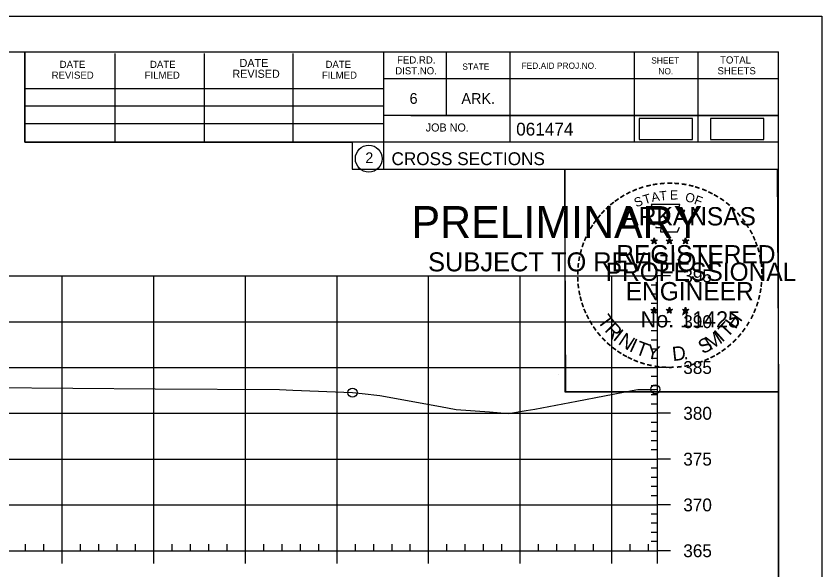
# Model space of a CAD drawing. Extents: x 1359801 to 1362404, y 372415 to 374228.
# Drawn here: x 1361894.9 to 1361982.8, y 372674.2 to 372734.6 of the extents above; entities that cross this region are included whole.
import ezdxf

# ---------------------------------------------------------------- set-up
doc = ezdxf.new("R2010")
doc.units = 0
for name, color, linetype in [('S_DRG_PT_SYM', 7, 'Continuous'), ('S_MAILBOX', 7, 'Continuous'), ('S_PRIMARY_CTL', 7, 'Continuous'), ('S_PRIMARY_CTL_ANNOT', 7, 'Continuous'), ('S_SHOULDER', 7, 'Continuous'), ('S_TELEPHONE_UTILITIES', 7, 'Continuous'), ('S_UNDERGROUND_CABLE', 7, 'Continuous'), ('S_UTL_PT_SYM', 7, 'Continuous'), ('S_WATER_UTILITIES', 7, 'Continuous')]:
    doc.layers.add(name, color=color, linetype=linetype)

msp = doc.modelspace()

# ---------------------------------------------------------------- linework, layer by layer
at = {"layer": 'S_DRG_PT_SYM'}
msp.add_lwpolyline([(1361821.284, 372693.939), (1361856.016, 372694.14), (1361874.05, 372694.226), (1361910.048, 372693.936), (1361923.612, 372693.836), (1361925.075, 372693.774), (1361931.575, 372693.503), (1361932.614, 372693.403), (1361934.572, 372693.207), (1361941.182, 372691.986), (1361942.877, 372691.662), (1361946.529, 372691.397), (1361948.625, 372691.234), (1361950.541, 372691.539), (1361951.497, 372691.687), (1361956.053, 372692.567), (1361962.106, 372693.736), (1361962.718, 372693.849), (1361962.822, 372693.849), (1361964.639, 372693.862), (1361964.89, 372693.87)], dxfattribs=at)
at = {"layer": 'S_MAILBOX'}
for p, q in [((1361674.89, 372706.246), (1361964.89, 372706.246)), ((1361899.89, 372676.246), (1361899.89, 372706.246)), ((1361909.89, 372676.246), (1361909.89, 372706.246)), ((1361919.89, 372676.246), (1361919.89, 372706.246)), ((1361929.89, 372676.246), (1361929.89, 372706.246)), ((1361939.89, 372676.246), (1361939.89, 372706.246)), ((1361949.89, 372676.246), (1361949.89, 372706.246)), ((1361959.89, 372676.246), (1361959.89, 372706.246)), ((1361964.89, 372676.246), (1361964.89, 372706.246)), ((1361674.89, 372701.246), (1361964.89, 372701.246)), ((1361674.89, 372696.246), (1361964.89, 372696.246)), ((1361674.89, 372691.246), (1361964.89, 372691.246)), ((1361674.89, 372686.246), (1361964.89, 372686.246)), ((1361674.89, 372681.246), (1361964.89, 372681.246)), ((1361674.89, 372676.246), (1361964.89, 372676.246))]:
    msp.add_line(p, q, dxfattribs=at)
at = {"layer": 'S_SHOULDER'}
for p, q in [((1361649.489, 372734.6), (1361982.823, 372734.6)), ((1361954.105, 372695.45), (1361954.105, 372695.45))]:
    msp.add_line(p, q, dxfattribs=at)
for points in [[(1361649.483, 372734.6), (1361982.823, 372734.6), (1361982.823, 372521.263), (1361649.483, 372521.263)], [(1361895.81, 372730.706), (1361895.81, 372720.826), (1361931.542, 372720.826), (1361931.542, 372717.906), (1361954.742, 372717.906), (1361954.742, 372693.573), (1361978.07, 372693.573), (1361978.07, 372525.246), (1361661.89, 372525.246), (1361661.89, 372730.706)], [(1361954.742, 372717.906), (1361977.95, 372717.906), (1361978.07, 372693.573), (1361954.862, 372693.573)]]:
    msp.add_lwpolyline(points, close=True, dxfattribs=at)
for centre in [(1361931.575, 372693.503), (1361964.639, 372693.862)]:
    msp.add_circle(centre, 0.5, dxfattribs=at)
at = {"layer": 'S_TELEPHONE_UTILITIES'}
for p, q in [((1361964.155, 372710.161), (1361964.504, 372710.05)), ((1361964.155, 372710.161), (1361964.408, 372710.116)), ((1361964.155, 372710.161), (1361964.392, 372710.039)), ((1361964.288, 372709.753), (1361964.504, 372710.05)), ((1361964.288, 372709.753), (1361964.414, 372709.997)), ((1361964.288, 372709.753), (1361964.502, 372709.97)), ((1361964.504, 372710.415), (1361964.463, 372710.163)), ((1361964.717, 372709.753), (1361964.502, 372709.967)), ((1361964.504, 372710.05), (1361964.504, 372710.415)), ((1361964.504, 372710.415), (1361964.553, 372710.165)), ((1361964.851, 372710.161), (1361964.504, 372710.05)), ((1361964.717, 372709.753), (1361964.504, 372710.05)), ((1361964.851, 372710.161), (1361964.565, 372710.112)), ((1361964.717, 372709.753), (1361964.58, 372710.044)), ((1361964.851, 372710.161), (1361964.647, 372710.059)), ((1361965.825, 372710.161), (1361966.174, 372710.05)), ((1361965.825, 372710.161), (1361966.078, 372710.116)), ((1361965.825, 372710.161), (1361966.062, 372710.039)), ((1361965.958, 372709.753), (1361966.174, 372710.05)), ((1361965.958, 372709.753), (1361966.084, 372709.997)), ((1361965.958, 372709.753), (1361966.172, 372709.97)), ((1361966.174, 372710.415), (1361966.133, 372710.163)), ((1361966.387, 372709.753), (1361966.172, 372709.967)), ((1361966.174, 372710.05), (1361966.174, 372710.415)), ((1361966.174, 372710.415), (1361966.223, 372710.165)), ((1361966.521, 372710.161), (1361966.174, 372710.05)), ((1361966.387, 372709.753), (1361966.174, 372710.05)), ((1361966.521, 372710.161), (1361966.235, 372710.112)), ((1361966.387, 372709.753), (1361966.25, 372710.044)), ((1361966.521, 372710.161), (1361966.317, 372710.059)), ((1361967.589, 372710.149), (1361967.938, 372710.038)), ((1361967.589, 372710.149), (1361967.842, 372710.104)), ((1361967.589, 372710.149), (1361967.826, 372710.027)), ((1361967.722, 372709.741), (1361967.938, 372710.038)), ((1361967.722, 372709.741), (1361967.848, 372709.985)), ((1361967.722, 372709.741), (1361967.936, 372709.958)), ((1361967.938, 372710.403), (1361967.897, 372710.151)), ((1361968.151, 372709.741), (1361967.936, 372709.955)), ((1361967.938, 372710.038), (1361967.938, 372710.403)), ((1361967.938, 372710.403), (1361967.987, 372710.153)), ((1361968.285, 372710.149), (1361967.938, 372710.038)), ((1361968.151, 372709.741), (1361967.938, 372710.038)), ((1361968.285, 372710.149), (1361967.999, 372710.1)), ((1361968.151, 372709.741), (1361968.014, 372710.032)), ((1361968.285, 372710.149), (1361968.081, 372710.047)), ((1361964.5, 372702.842), (1361964.459, 372702.59)), ((1361964.5, 372702.477), (1361964.5, 372702.842)), ((1361964.5, 372702.842), (1361964.549, 372702.592)), ((1361966.169, 372702.842), (1361966.128, 372702.59)), ((1361966.169, 372702.477), (1361966.169, 372702.842)), ((1361966.169, 372702.842), (1361966.218, 372702.592)), ((1361967.936, 372702.832), (1361967.895, 372702.58)), ((1361967.936, 372702.467), (1361967.936, 372702.832)), ((1361967.936, 372702.832), (1361967.985, 372702.582)), ((1361964.151, 372702.588), (1361964.5, 372702.477)), ((1361964.151, 372702.588), (1361964.404, 372702.543)), ((1361964.151, 372702.588), (1361964.388, 372702.466)), ((1361964.284, 372702.18), (1361964.5, 372702.477)), ((1361964.284, 372702.18), (1361964.41, 372702.424)), ((1361964.284, 372702.18), (1361964.498, 372702.397)), ((1361964.713, 372702.18), (1361964.498, 372702.394)), ((1361964.847, 372702.588), (1361964.5, 372702.477)), ((1361964.713, 372702.18), (1361964.5, 372702.477)), ((1361964.847, 372702.588), (1361964.561, 372702.539)), ((1361964.713, 372702.18), (1361964.576, 372702.471)), ((1361964.847, 372702.588), (1361964.643, 372702.486)), ((1361965.82, 372702.588), (1361966.169, 372702.477)), ((1361965.82, 372702.588), (1361966.073, 372702.543)), ((1361965.82, 372702.588), (1361966.057, 372702.466)), ((1361965.953, 372702.18), (1361966.169, 372702.477)), ((1361965.953, 372702.18), (1361966.079, 372702.424)), ((1361965.953, 372702.18), (1361966.167, 372702.397)), ((1361966.382, 372702.18), (1361966.167, 372702.394)), ((1361966.516, 372702.588), (1361966.169, 372702.477)), ((1361966.382, 372702.18), (1361966.169, 372702.477)), ((1361966.516, 372702.588), (1361966.23, 372702.539)), ((1361966.382, 372702.18), (1361966.245, 372702.471)), ((1361966.516, 372702.588), (1361966.312, 372702.486)), ((1361967.587, 372702.578), (1361967.936, 372702.467)), ((1361967.587, 372702.578), (1361967.84, 372702.533)), ((1361967.587, 372702.578), (1361967.824, 372702.456)), ((1361967.72, 372702.17), (1361967.936, 372702.467)), ((1361967.72, 372702.17), (1361967.846, 372702.414)), ((1361967.72, 372702.17), (1361967.934, 372702.387)), ((1361968.149, 372702.17), (1361967.934, 372702.384)), ((1361968.283, 372702.578), (1361967.936, 372702.467)), ((1361968.149, 372702.17), (1361967.936, 372702.467)), ((1361968.283, 372702.578), (1361967.997, 372702.529)), ((1361968.149, 372702.17), (1361968.012, 372702.461)), ((1361968.283, 372702.578), (1361968.079, 372702.476))]:
    msp.add_line(p, q, dxfattribs=at)
for points in [[(1361964.196, 372714.039), (1361964.465, 372713.212)], [(1361967.707, 372713.117), (1361967.849, 372713.401), (1361967.164, 372713.377), (1361967.312, 372714.039), (1361964.196, 372714.039)], [(1361964.688, 372711.616), (1361964.688, 372711.529), (1361965.251, 372711.51), (1361965.197, 372711.037), (1361967.067, 372711.037), (1361967.268, 372711.573)], [(1361964.504, 372710.415), (1361964.717, 372709.753), (1361964.155, 372710.161), (1361964.851, 372710.161), (1361964.288, 372709.753), (1361964.504, 372710.415)], [(1361966.174, 372710.415), (1361966.387, 372709.753), (1361965.825, 372710.161), (1361966.521, 372710.161), (1361965.958, 372709.753), (1361966.174, 372710.415)], [(1361967.938, 372710.403), (1361968.151, 372709.741), (1361967.589, 372710.149), (1361968.285, 372710.149), (1361967.722, 372709.741), (1361967.938, 372710.403)], [(1361964.5, 372702.842), (1361964.713, 372702.18), (1361964.151, 372702.588), (1361964.847, 372702.588), (1361964.284, 372702.18), (1361964.5, 372702.842)], [(1361966.169, 372702.842), (1361966.382, 372702.18), (1361965.82, 372702.588), (1361966.516, 372702.588), (1361965.953, 372702.18), (1361966.169, 372702.842)], [(1361967.936, 372702.832), (1361968.149, 372702.17), (1361967.587, 372702.578), (1361968.283, 372702.578), (1361967.72, 372702.17), (1361967.936, 372702.832)]]:
    msp.add_lwpolyline(points, dxfattribs=at)
for centre, radius in [((1361964.503, 372710.049), 0.172), ((1361964.503, 372710.049), 0.145), ((1361964.503, 372710.049), 0.116), ((1361964.503, 372710.049), 0.0991), ((1361964.503, 372710.049), 0.0747), ((1361964.503, 372710.049), 0.0495), ((1361964.503, 372710.049), 0.0296), ((1361966.173, 372710.049), 0.172), ((1361966.173, 372710.049), 0.145), ((1361966.173, 372710.049), 0.116), ((1361966.173, 372710.049), 0.0991), ((1361966.173, 372710.049), 0.0747), ((1361966.173, 372710.049), 0.0495), ((1361966.173, 372710.049), 0.0296), ((1361967.937, 372710.037), 0.172), ((1361967.937, 372710.037), 0.145), ((1361967.937, 372710.037), 0.116), ((1361967.937, 372710.037), 0.0991), ((1361967.937, 372710.037), 0.0747), ((1361967.937, 372710.037), 0.0495), ((1361967.937, 372710.037), 0.0296), ((1361964.499, 372702.476), 0.172), ((1361964.499, 372702.476), 0.145), ((1361964.499, 372702.476), 0.116), ((1361966.168, 372702.476), 0.172), ((1361966.168, 372702.476), 0.145), ((1361966.168, 372702.476), 0.116), ((1361967.935, 372702.466), 0.172), ((1361967.935, 372702.466), 0.145), ((1361964.499, 372702.476), 0.0991), ((1361964.499, 372702.476), 0.0747), ((1361964.499, 372702.476), 0.0495), ((1361964.499, 372702.476), 0.0296), ((1361966.168, 372702.476), 0.0991), ((1361966.168, 372702.476), 0.0747), ((1361966.168, 372702.476), 0.0495), ((1361966.168, 372702.476), 0.0296), ((1361967.935, 372702.466), 0.116), ((1361967.935, 372702.466), 0.0991), ((1361967.935, 372702.466), 0.0747), ((1361967.935, 372702.466), 0.0495), ((1361967.935, 372702.466), 0.0296)]:
    msp.add_circle(centre, radius, dxfattribs=at)
at = {"layer": 'S_UNDERGROUND_CABLE'}
for points in [[(1361962.88, 372721.124), (1361968.713, 372721.124), (1361968.713, 372723.434), (1361962.88, 372723.434)], [(1361970.649, 372721.13), (1361976.482, 372721.13), (1361976.482, 372723.44), (1361970.649, 372723.44)]]:
    msp.add_lwpolyline(points, close=True, dxfattribs=at)
at = {"layer": 'S_UTL_PT_SYM'}
for p, q in [((1361661.89, 372730.706), (1361978.07, 372730.706)), ((1361895.81, 372720.826), (1361895.81, 372730.706)), ((1361905.67, 372720.826), (1361905.67, 372730.506)), ((1361915.43, 372720.826), (1361915.43, 372730.506)), ((1361925.11, 372720.826), (1361925.11, 372730.506)), ((1361934.97, 372730.706), (1361934.97, 372717.906)), ((1361941.81, 372730.706), (1361941.81, 372723.766)), ((1361948.75, 372730.706), (1361948.75, 372720.826)), ((1361962.33, 372730.706), (1361962.33, 372720.826)), ((1361969.27, 372730.706), (1361969.27, 372720.826)), ((1361978.07, 372525.246), (1361978.07, 372730.706)), ((1361978.07, 372727.766), (1361934.97, 372727.766)), ((1361978.07, 372727.786), (1361978.07, 372727.786)), ((1361895.81, 372726.686), (1361934.97, 372726.686)), ((1361895.81, 372724.826), (1361934.97, 372724.826)), ((1361978.07, 372723.766), (1361934.97, 372723.766)), ((1361937.93, 372723.766), (1361978.07, 372723.766)), ((1361895.81, 372720.826), (1361895.81, 372722.886)), ((1361895.81, 372722.886), (1361934.97, 372722.886)), ((1361978.07, 372720.826), (1361895.81, 372720.826)), ((1361934.97, 372717.906), (1361978.07, 372717.906))]:
    msp.add_line(p, q, dxfattribs=at)
msp.add_circle((1361933.357, 372719.041), 1.467, dxfattribs=at)
at = {"layer": 'S_WATER_UTILITIES'}
for p, q in [((1361964.89, 372676.246), (1361964.89, 372706.246)), ((1361966.29, 372706.246), (1361964.89, 372706.246)), ((1361964.89, 372705.246), (1361964.19, 372705.246)), ((1361964.89, 372704.246), (1361964.19, 372704.246)), ((1361964.89, 372703.246), (1361964.19, 372703.246)), ((1361964.89, 372702.246), (1361964.19, 372702.246)), ((1361966.29, 372701.246), (1361964.89, 372701.246)), ((1361964.89, 372700.246), (1361964.19, 372700.246)), ((1361964.89, 372699.246), (1361964.19, 372699.246)), ((1361964.89, 372698.246), (1361964.19, 372698.246)), ((1361964.89, 372697.246), (1361964.19, 372697.246)), ((1361966.29, 372696.246), (1361964.89, 372696.246)), ((1361964.89, 372695.246), (1361964.19, 372695.246)), ((1361964.89, 372694.246), (1361964.19, 372694.246)), ((1361964.89, 372693.246), (1361964.19, 372693.246)), ((1361964.89, 372692.246), (1361964.19, 372692.246)), ((1361966.29, 372691.246), (1361964.89, 372691.246)), ((1361964.89, 372690.246), (1361964.19, 372690.246)), ((1361964.89, 372689.246), (1361964.19, 372689.246)), ((1361964.89, 372688.246), (1361964.19, 372688.246)), ((1361964.89, 372687.246), (1361964.19, 372687.246)), ((1361966.29, 372686.246), (1361964.89, 372686.246)), ((1361964.89, 372685.246), (1361964.19, 372685.246)), ((1361964.89, 372684.246), (1361964.19, 372684.246)), ((1361964.89, 372683.246), (1361964.19, 372683.246)), ((1361964.89, 372682.246), (1361964.19, 372682.246)), ((1361966.29, 372681.246), (1361964.89, 372681.246)), ((1361964.89, 372680.246), (1361964.19, 372680.246)), ((1361964.89, 372679.246), (1361964.19, 372679.246)), ((1361964.89, 372678.246), (1361964.19, 372678.246)), ((1361964.89, 372677.246), (1361964.19, 372677.246)), ((1361674.89, 372676.246), (1361964.89, 372676.246)), ((1361895.89, 372676.246), (1361895.89, 372676.946)), ((1361897.89, 372676.246), (1361897.89, 372676.946)), ((1361899.89, 372674.846), (1361899.89, 372676.246)), ((1361901.89, 372676.246), (1361901.89, 372676.946)), ((1361903.89, 372676.246), (1361903.89, 372676.946)), ((1361905.89, 372676.246), (1361905.89, 372676.946)), ((1361907.89, 372676.246), (1361907.89, 372676.946)), ((1361909.89, 372674.846), (1361909.89, 372676.246)), ((1361911.89, 372676.246), (1361911.89, 372676.946)), ((1361913.89, 372676.246), (1361913.89, 372676.946)), ((1361915.89, 372676.246), (1361915.89, 372676.946)), ((1361917.89, 372676.246), (1361917.89, 372676.946)), ((1361919.89, 372674.846), (1361919.89, 372676.246)), ((1361921.89, 372676.246), (1361921.89, 372676.946)), ((1361923.89, 372676.246), (1361923.89, 372676.946)), ((1361925.89, 372676.246), (1361925.89, 372676.946)), ((1361927.89, 372676.246), (1361927.89, 372676.946)), ((1361929.89, 372674.846), (1361929.89, 372676.246)), ((1361931.89, 372676.246), (1361931.89, 372676.946)), ((1361933.89, 372676.246), (1361933.89, 372676.946)), ((1361935.89, 372676.246), (1361935.89, 372676.946)), ((1361937.89, 372676.246), (1361937.89, 372676.946)), ((1361939.89, 372674.846), (1361939.89, 372676.246)), ((1361941.89, 372676.246), (1361941.89, 372676.946)), ((1361943.89, 372676.246), (1361943.89, 372676.946)), ((1361945.89, 372676.246), (1361945.89, 372676.946)), ((1361947.89, 372676.246), (1361947.89, 372676.946)), ((1361949.89, 372674.846), (1361949.89, 372676.246)), ((1361951.89, 372676.246), (1361951.89, 372676.946)), ((1361953.89, 372676.246), (1361953.89, 372676.946)), ((1361955.89, 372676.246), (1361955.89, 372676.946)), ((1361957.89, 372676.246), (1361957.89, 372676.946)), ((1361959.89, 372674.846), (1361959.89, 372676.246)), ((1361961.89, 372676.246), (1361961.89, 372676.946)), ((1361963.89, 372676.246), (1361963.89, 372676.946)), ((1361964.89, 372674.846), (1361964.89, 372676.246)), ((1361966.29, 372676.246), (1361964.89, 372676.246))]:
    msp.add_line(p, q, dxfattribs=at)

# ---------------------------------------------------------------- texts
at = {"layer": 'S_PRIMARY_CTL'}
for s, p in [('395', (1361967.69, 372705.546)), ('390', (1361967.69, 372700.546)), ('385', (1361967.69, 372695.546)), ('380', (1361967.69, 372690.546)), ('375', (1361967.69, 372685.546)), ('370', (1361967.69, 372680.546)), ('365', (1361967.69, 372675.546))]:
    msp.add_text(s, height=1.4, dxfattribs=at).set_placement(p)
at = {"layer": 'S_PRIMARY_CTL_ANNOT'}
for s, height, p in [('PRELIMINARY', 3.5, (1361938.021, 372710.369)), ('DWB', 0.01, (1361938.768, 372712.218)), ('SUBJECT TO REVISION', 2.07511, (1361939.83, 372706.74))]:
    msp.add_text(s, height=height, rotation=360, dxfattribs=at).set_placement(p)
at = {"layer": 'S_SHOULDER'}
msp.add_text('+', height=0.1, dxfattribs=at).set_placement((1361923.569, 372693.786))
at = {"layer": 'S_TELEPHONE_UTILITIES'}
for s, height, rotation, p in [('-', 1.6, 24.30721, (1361962.31, 372714.897)), ('-', 1.6, 19.17608, (1361962.944, 372715.166)), ('-', 1.6, 13.63015, (1361963.694, 372715.407)), ('-', 1.6, 10.21935, (1361964.372, 372715.569)), ('-', 1.6, 5.89682, (1361965.101, 372715.679)), ('-', 1.6, 0.18623, (1361965.873, 372715.751)), ('-', 1.6, 357.74304, (1361966.596, 372715.738)), ('-', 1.6, 352.16172, (1361967.34, 372715.682)), ('-', 1.6, 347.20489, (1361968.059, 372715.568)), ('-', 1.6, 342.3362, (1361968.694, 372715.413)), ('-', 1.6, 337.85509, (1361969.429, 372715.19)), ('-', 1.6, 34.06357, (1361961.08, 372714.21)), ('-', 1.6, 28.79182, (1361961.677, 372714.58)), ('T', 1, 16.4036, (1361963.465, 372714.048)), ('A', 1, 11.21318, (1361964.291, 372714.299)), ('T', 1, 6.02276, (1361965.14, 372714.465)), ('E', 1, 0.83234, (1361966.245, 372714.575)), ('O', 1, 350.4515, (1361967.849, 372714.365)), ('F', 1, 340.07066, (1361968.803, 372714.137)), ('-', 1.6, 334.12109, (1361970.06, 372714.919)), ('-', 1.6, 329.64089, (1361970.639, 372714.636)), ('-', 1.6, 38.95066, (1361960.026, 372713.437)), ('-', 1.6, 36.23174, (1361960.502, 372713.815)), ('S', 1, 21.59401, (1361962.551, 372713.717)), ('-', 1.6, 325.86266, (1361971.282, 372714.275)), ('-', 1.6, 320.52971, (1361971.892, 372713.849)), ('-', 1.6, 48.42305, (1361959.145, 372712.542)), ('-', 1.6, 42.96224, (1361959.593, 372713.02)), ('ARKANSAS', 2, 360, (1361961.049, 372711.751)), ('-', 1.6, 315.57859, (1361972.491, 372713.361)), ('-', 1.6, 309.87973, (1361973.06, 372712.811)), ('-', 1.6, 54.23247, (1361958.329, 372711.489)), ('-', 1.6, 50.61417, (1361958.742, 372712.056)), ('-', 1.6, 306.65218, (1361973.585, 372712.209)), ('-', 1.6, 58.07063, (1361958.004, 372710.962)), ('-', 1.4, 303.67529, (1361974.071, 372711.641)), ('-', 1.6, 67.77427, (1361957.432, 372709.737)), ('-', 1.6, 62.87135, (1361957.691, 372710.348)), ('-', 1.6, 299.66835, (1361974.39, 372711.034)), ('-', 1.6, 294.66279, (1361974.714, 372710.422)), ('-', 1.6, 72.39447, (1361957.213, 372709.107)), ('REGISTERED', 2, 360, (1361960.371, 372707.602)), ('DWB', 0.01, 360, (1361964.491, 372710.045)), ('DWB', 0.01, 360, (1361966.161, 372710.045)), ('DWB', 0.01, 360, (1361967.925, 372710.034)), ('-', 1.6, 290.57283, (1361974.971, 372709.845)), ('-', 1.6, 75.46096, (1361957.016, 372708.393)), ('-', 1.6, 285.12326, (1361975.205, 372709.265)), ('-', 1.6, 81.20126, (1361956.884, 372707.68)), ('-', 1.6, 280.54934, (1361975.405, 372708.523)), ('-', 1.6, 85.18634, (1361956.808, 372706.989)), ('PROFESSIONAL', 2, 360, (1361959.223, 372705.698)), ('-', 1.6, 276.59616, (1361975.567, 372707.755)), ('-', 1.6, 274.33011, (1361975.627, 372707.033)), ('-', 1.6, 94.19588, (1361956.818, 372705.563)), ('-', 1.6, 89.06224, (1361956.783, 372706.288)), ('-', 1.6, 269.94067, (1361975.661, 372706.401)), ('-', 1.6, 98.94793, (1361956.89, 372704.896)), ('ENGINEER', 2, 360, (1361961.41, 372703.573)), ('-', 1.6, 263.5172, (1361975.642, 372705.735)), ('-', 1.6, 101.71495, (1361957.025, 372704.163)), ('-', 1.6, 260.99529, (1361975.571, 372705.081)), ('-', 1.6, 105.45785, (1361957.187, 372703.568)), ('-', 1.6, 255.7626, (1361975.461, 372704.403)), ('-', 1.6, 109.08742, (1361957.402, 372702.937)), ('-', 1.6, 114.06432, (1361957.656, 372702.341)), ('-', 1.6, 247.88866, (1361975.057, 372703.01)), ('-', 1.6, 252.86809, (1361975.28, 372703.683)), ('-', 1.6, 115.72885, (1361957.961, 372701.723)), ('T', 1.54, 306.04056, (1361958.26, 372701.315)), ('No. 11425', 1.757, 360, (1361963.038, 372700.622)), ('DWB', 0.01, 360, (1361964.487, 372702.472)), ('DWB', 0.01, 360, (1361966.156, 372702.472)), ('DWB', 0.01, 360, (1361967.923, 372702.462)), ('H', 1.54, 54.60883, (1361973.38, 372700.35)), ('-', 1.6, 244.61971, (1361974.795, 372702.381)), ('-', 1.6, 120.44712, (1361958.318, 372701.137)), ('R', 1.54, 314.00497, (1361959.022, 372700.267)), ('T', 1.54, 46.64442, (1361972.49, 372699.408)), ('-', 1.6, 239.07125, (1361974.401, 372701.629)), ('-', 1.6, 125.89344, (1361958.721, 372700.576)), ('-', 1.6, 130.71812, (1361959.183, 372700.024)), ('I', 1.54, 321.96938, (1361959.923, 372699.335)), ('N', 1.54, 326.50021, (1361960.49, 372698.864)), ('M', 1.54, 32.65632, (1361970.645, 372698.083)), ('I', 1.54, 42.11359, (1361971.929, 372698.93)), ('-', 1.6, 231.25377, (1361973.569, 372700.41)), ('-', 1.6, 233.84524, (1361973.999, 372700.976)), ('-', 1.6, 134.22381, (1361959.7, 372699.479)), ('I', 1.54, 335.36034, (1361961.698, 372698.078)), ('T', 1.54, 339.89117, (1361962.359, 372697.75)), ('S', 1.54, 26.9312, (1361969.806, 372697.677)), ('-', 1.6, 225.76533, (1361973.09, 372699.846)), ('-', 1.6, 138.93382, (1361960.225, 372699.015)), ('-', 1.6, 144.64634, (1361960.781, 372698.609)), ('Y', 1.54, 347.85558, (1361963.576, 372697.305)), ('D', 1.54, 6.39691, (1361966.561, 372696.946)), ('-', 1.6, 215.73633, (1361972.019, 372698.865)), ('-', 1.6, 221.08509, (1361972.568, 372699.337)), ('-', 1.6, 148.08978, (1361961.342, 372698.238)), ('-', 1.6, 151.57039, (1361961.921, 372697.913)), ('-', 1.6, 154.60019, (1361962.443, 372697.666)), ('.', 1.54, 13.76417, (1361967.753, 372697.074)), ('-', 1.6, 207.35684, (1361970.927, 372698.132)), ('-', 1.6, 212.24909, (1361971.485, 372698.478)), ('-', 1.6, 158.56121, (1361963.067, 372697.412)), ('-', 1.6, 162.79826, (1361963.754, 372697.199)), ('-', 1.6, 167.55551, (1361964.469, 372697.035)), ('-', 1.6, 173.11546, (1361965.241, 372696.925)), ('-', 1.6, 185.81666, (1361967.542, 372696.967)), ('-', 1.6, 191.28576, (1361968.278, 372697.099)), ('-', 1.6, 195.47429, (1361969.007, 372697.298)), ('-', 1.6, 200.71842, (1361969.684, 372697.54)), ('-', 1.6, 204.25161, (1361970.303, 372697.813)), ('-', 1.6, 176.51827, (1361965.989, 372696.872)), ('-', 1.6, 181.59176, (1361966.733, 372696.891))]:
    msp.add_text(s, height=height, rotation=rotation, dxfattribs=at).set_placement(p)
at = {"layer": 'S_UTL_PT_SYM'}
for s, height, p in [('DATE', 0.8792, (1361919.25, 372729.046)), ('FED.RD.', 0.7819, (1361936.45, 372729.426)), ('SHEET', 0.684, (1361964.19, 372729.426)), ('TOTAL', 0.7819, (1361971.71, 372729.426)), ('DATE', 0.7819, (1361899.61, 372728.946)), ('DATE', 0.7819, (1361909.47, 372728.946)), ('DATE', 0.7819, (1361928.63, 372728.946)), ('DIST.NO.', 0.7819, (1361936.25, 372728.246)), ('STATE', 0.684, (1361943.57, 372728.746)), ('FED.AID PROJ.NO.', 0.684, (1361950.03, 372728.846)), ('SHEETS', 0.7819, (1361971.43, 372728.246)), ('REVISED', 0.7819, (1361898.73, 372727.766)), ('FILMED', 0.7819, (1361908.89, 372727.766)), ('REVISED', 0.8792, (1361918.47, 372727.866)), ('FILMED', 0.7819, (1361928.23, 372727.766)), ('NO.', 0.684, (1361964.97, 372728.246)), ('6', 1.172, (1361937.81, 372725.026)), ('ARK.', 1.1723, (1361943.47, 372725.026)), ('JOB NO.', 0.8792, (1361939.57, 372722.006)), ('061474', 1.4, (1361949.446, 372721.565)), ('2', 1.172, (1361932.974, 372718.555)), ('CROSS SECTIONS', 1.4, (1361935.834, 372718.336))]:
    msp.add_text(s, height=height, rotation=360, dxfattribs=at).set_placement(p)

doc.saveas('drawing.dxf')
